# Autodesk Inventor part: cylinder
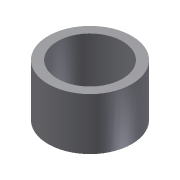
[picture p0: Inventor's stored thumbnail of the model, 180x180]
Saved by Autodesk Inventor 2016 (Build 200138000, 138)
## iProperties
Shininess: 64.0
Length Units: 11269
Angle Units: 11279
Time Units: 11290
Mass Units: 11283
Length Display Precision: 3
Angle Display Precision: 2
Compacted: True
Part Number: cylinder
Document SubType Name: Modeling
Created: 2003-01
Designer: Owner
Density: 1 g/cm^3
Material: Generic
Appearance: Default
Density: 0.0
Volumn: 0.0
Area: 0.0
PropertySet Name: Model Information
Control State: 0
Master: False
Checked Out: False
Author: Owner
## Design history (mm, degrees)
sketch "Sketch1"
  geometry: C1 r 112.5 at (0, 0); C2 r 87.5 at (0, 0)
  constraints: 2 centre point, 1 coincident, 1 concentric
  dimensions: "d0" = 225 diameter of C1; "d1" = 175 diameter of C2
extrude "Extrusion1" new body sketch "Sketch1" stored distance "d2" = 140; taper "d3" = 0 deg
body "Solid1"
